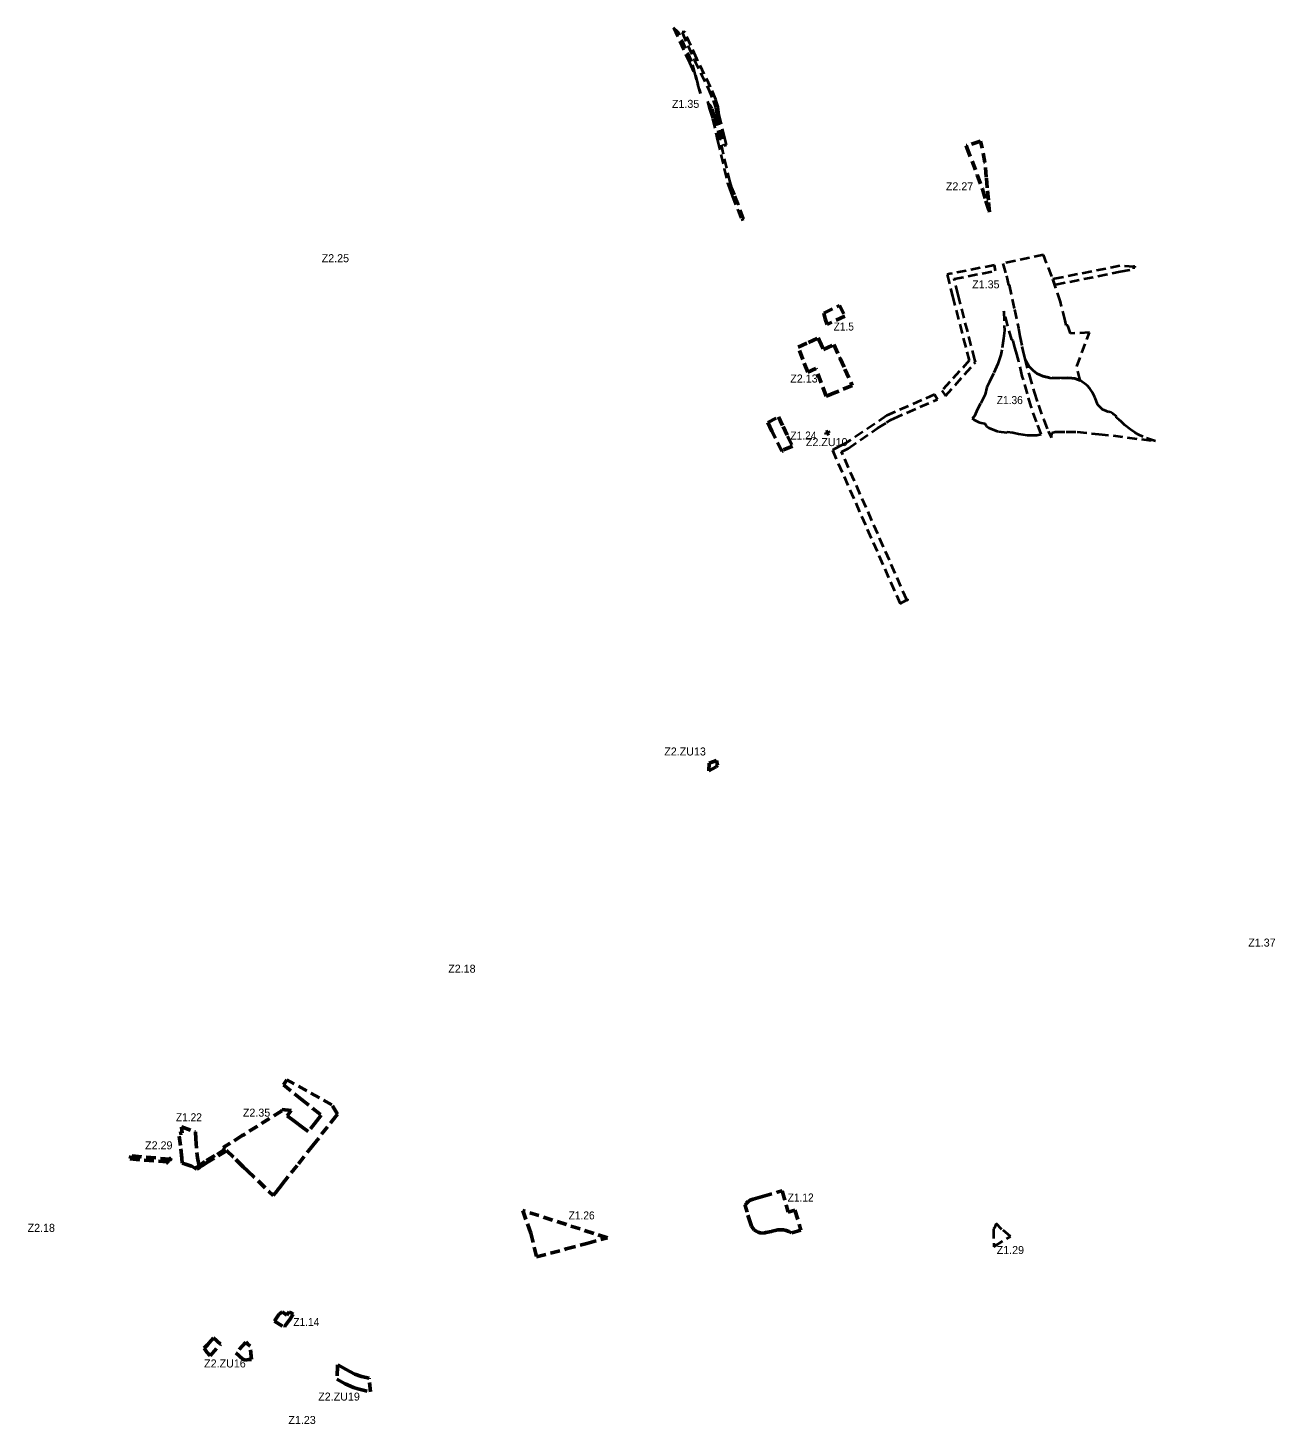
# Model space of a CAD drawing. Extents: x -650368 to -643203, y -1074215 to -1066658.
# Drawn here: x -650368 to -647095, y -1070321 to -1066658 of the extents above; entities that cross this region are included whole.
import ezdxf
from ezdxf.enums import TextEntityAlignment as Align

# ---------------------------------------------------------------- set-up
doc = ezdxf.new("R2010")
doc.units = 0
doc.header["$LTSCALE"] = 8.4
doc.header["$PDMODE"] = 32
doc.header["$PDSIZE"] = 4.2
doc.linetypes.add('MEDIUM_DASHED', pattern=[4.5, 3, -1.5])
doc.layers.add('57', color=7, linetype='MEDIUM_DASHED', lineweight=40)
doc.layers.add('58', color=7, linetype='MEDIUM_DASHED', lineweight=53)
for name, color, linetype in [('60', 7, 'Continuous'), ('61', 7, 'Continuous'), ('62', 7, 'Continuous')]:
    doc.layers.add(name, color=color, linetype=linetype)

msp = doc.modelspace()

# ---------------------------------------------------------------- linework, layer by layer
at = {"layer": '57'}
for p, q in [((-648495.63, -1067161.363), (-648489.1, -1067158.84)), ((-647408.2, -1067742.37), (-647440.81, -1067731.38))]:
    msp.add_line(p, q, dxfattribs=at)
for points in [[(-648602.97, -1066830.11), (-648616.86, -1066779.79), (-648625.44, -1066746.45), (-648659.95, -1066670.89), (-648662.46, -1066668.53), (-648673.407, -1066658.275), (-648631.791, -1066749.394)], [(-648576.145, -1066813.802), (-648612.763, -1066739.165), (-648643.925, -1066668.483), (-648651.042, -1066669.551), (-648651.1, -1066669.56)], [(-648651.1, -1066669.56), (-648619.11, -1066742.12), (-648582.52, -1066816.7)], [(-648631.791, -1066749.394), (-648616.104, -1066782.727), (-648602.97, -1066830.11)], [(-648582.52, -1066816.7), (-648569.13, -1066848.61), (-648566.63, -1066856.72), (-648563.48, -1066866.96), (-648560.2, -1066888.58), (-648541.521, -1066966.657), (-648534.701, -1066965.077), (-648538.812, -1066947.891)], [(-648538.812, -1066947.891), (-648553.323, -1066887.238), (-648556.637, -1066865.397), (-648559.94, -1066854.66), (-648562.542, -1066846.219), (-648576.145, -1066813.802)], [(-648571.96, -1066869.37), (-648577.99, -1066860.17), (-648583.94, -1066851.11), (-648578.702, -1066871.259)], [(-648578.702, -1066871.259), (-648571.167, -1066896.326), (-648557.816, -1066953.444)], [(-648489.1, -1067158.84), (-648512.95, -1067095.97), (-648520.4, -1067077.42), (-648524.93, -1067063.35), (-648533.66, -1067026), (-648551, -1066951.85), (-648564.4, -1066894.52), (-648571.96, -1066869.37)], [(-648557.816, -1066953.444), (-648540.476, -1067027.594), (-648531.681, -1067065.222)], [(-648531.681, -1067065.222), (-648526.988, -1067079.8), (-648519.471, -1067098.516), (-648495.644, -1067161.326)], [(-647638.68, -1067439.06), (-647642.686, -1067438.46), (-647645.78, -1067425.81), (-647658.13, -1067376.99), (-647680.64, -1067310.37), (-647702.42, -1067253.98), (-647809.02, -1067276.271)], [(-647809.02, -1067276.271), (-647799.76, -1067308.3), (-647794.54, -1067333.14)], [(-647948.488, -1067303.671), (-647955.805, -1067305.106), (-647941.289, -1067362.104)], [(-647882.66, -1067529.231), (-647926.759, -1067358.379), (-647937.355, -1067316.774), (-647828.376, -1067295.406), (-647828.104, -1067295.352), (-647831.28, -1067280.69), (-647948.488, -1067303.671)], [(-647465.203, -1067285.115), (-647501.968, -1067282.642), (-647673.685, -1067316.666), (-647678.21, -1067317.562), (-647673.367, -1067331.895), (-647670.77, -1067331.38), (-647501.099, -1067297.762)], [(-647501.099, -1067297.762), (-647465.699, -1067290.747), (-647465.203, -1067285.115)], [(-647794.54, -1067333.14), (-647792.52, -1067332.74), (-647778.78, -1067397.1), (-647768.5, -1067446.04), (-647764.89, -1067466.64), (-647759.16, -1067494.01)], [(-647941.289, -1067362.104), (-647897.637, -1067531.223), (-647969.29, -1067609.79), (-647959.832, -1067623.65)], [(-647773.96, -1067508.48), (-647777.55, -1067496.95), (-647781.85, -1067479.19), (-647785.64, -1067477.02), (-647806.8, -1067401.51), (-647804.88, -1067452.07), (-647807.17, -1067473.06), (-647811.8, -1067502.42), (-647814.89, -1067515.91), (-647822.82, -1067539.89), (-647833.51, -1067565.03), (-647844.04, -1067587.17)], [(-647751.41, -1067526.58), (-647740.124, -1067546.265), (-647729.802, -1067557.462), (-647719.661, -1067564.884), (-647704.458, -1067572.034), (-647685.968, -1067576.68), (-647654.743, -1067576.996), (-647640.087, -1067576.306), (-647628.441, -1067576.759), (-647620.586, -1067578.478), (-647606.559, -1067583.309), (-647614.75, -1067546.53), (-647582.2, -1067457.65), (-647631.59, -1067459.72), (-647638.68, -1067439.06)], [(-647759.16, -1067494.01), (-647756.55, -1067505.32), (-647751.41, -1067526.58)], [(-647959.832, -1067623.65), (-647881.085, -1067535.333), (-647882.66, -1067529.231)], [(-647708.71, -1067723.99), (-647721.05, -1067691.73), (-647734.63, -1067652.57), (-647744.61, -1067617.96), (-647758.25, -1067571.79), (-647768.5, -1067529.75), (-647773.96, -1067508.48)], [(-647547.663, -1067659.519), (-647560.187, -1067647.458), (-647567.744, -1067627.24), (-647573.605, -1067614.951), (-647580.539, -1067604.432), (-647586.864, -1067597.411), (-647591.227, -1067593.613), (-647604.415, -1067584.047), (-647620.586, -1067578.478), (-647628.441, -1067576.759), (-647640.087, -1067576.306), (-647654.743, -1067576.996), (-647685.968, -1067576.68), (-647704.458, -1067572.034), (-647719.661, -1067564.884), (-647729.802, -1067557.462), (-647740.124, -1067546.265), (-647751.41, -1067526.58)], [(-647751.41, -1067526.58), (-647740.49, -1067568.67), (-647727.37, -1067614.33), (-647715.92, -1067648.12), (-647702.04, -1067686.86), (-647690.09, -1067716.05), (-647681.91, -1067732.74)], [(-647844.04, -1067587.17), (-647850.96, -1067600.4), (-647855.65, -1067620.33), (-647867.53, -1067643.84)], [(-647988.235, -1067619.912), (-648114.145, -1067675.531), (-648222.872, -1067748.412), (-648238.748, -1067756.759), (-648256.499, -1067766.091), (-648079.002, -1068168.139), (-648061.329, -1068158.649)], [(-648215.115, -1067761.28), (-648137.869, -1067708.325), (-648114.323, -1067693.403), (-648103.383, -1067686.47), (-648103.298, -1067686.416), (-648095.475, -1067682.994), (-647983.403, -1067633.963), (-647983.06, -1067633.813), (-647980.561, -1067632.719), (-647982.95, -1067628.73), (-647988.235, -1067619.912)], [(-647867.53, -1067643.84), (-647876.15, -1067658.82), (-647883.78, -1067676.59), (-647886.95, -1067680.13), (-647889.94, -1067681.81)], [(-647889.94, -1067681.81), (-647884.25, -1067686.21), (-647882.82, -1067687.32), (-647871.87, -1067692.85), (-647869.32, -1067693.61), (-647865.76, -1067694.68), (-647856.9, -1067695.97)], [(-647499.095, -1067691.163), (-647503.97, -1067686.73), (-647510.6, -1067680.86), (-647511.24, -1067677.53), (-647517.74, -1067672.85), (-647520.13, -1067671.13), (-647527.76, -1067665.65), (-647530.82, -1067666.65), (-647536.83, -1067663.64), (-647547.663, -1067659.519)], [(-647856.9, -1067695.97), (-647852.3, -1067703.36), (-647845.74, -1067707.59), (-647821.02, -1067717.33), (-647798.5, -1067719.67), (-647798.17, -1067717.58), (-647783.13, -1067719.68), (-647768.53, -1067722.82), (-647745.41, -1067726.6), (-647732.71, -1067727.02), (-647720.45, -1067726.49), (-647708.71, -1067723.99)], [(-647681.91, -1067732.74), (-647680.804, -1067720.745), (-647672, -1067718), (-647643, -1067718), (-647614, -1067718), (-647557, -1067724), (-647520.145, -1067727.879), (-647408.2, -1067742.37)], [(-647440.81, -1067731.38), (-647453.87, -1067724.97), (-647462.45, -1067719.84), (-647474.13, -1067711.81), (-647489.3, -1067700.07), (-647499.095, -1067691.163)], [(-648061.329, -1068158.649), (-648232.676, -1067770.513), (-648215.115, -1067761.28)]]:
    msp.add_lwpolyline(points, dxfattribs=at)
at = {"layer": '57', "lineweight": 53}
for points in [[(-648279.24, -1067406.38), (-648237.881, -1067386.158), (-648237.873, -1067386.174), (-648237.865, -1067386.17), (-648224.19, -1067414.14), (-648270.02, -1067436.37), (-648275.41, -1067421.3)], [(-648397.98, -1067678.79), (-648385.86, -1067704.19), (-648373.99, -1067728.95), (-648361.08, -1067755.88), (-648387.04, -1067765.67), (-648386.12, -1067767.45), (-648389.29, -1067768.64), (-648415.164, -1067716.136), (-648426.366, -1067693.402)], [(-649967.81, -1069590.74), (-649971.38, -1069558.79), (-649963.43, -1069557.91), (-649965.26, -1069541.51), (-649928.48, -1069554.57), (-649927.304, -1069572.44), (-649924.62, -1069608.53), (-649923.17, -1069623.14), (-649918.354, -1069643.452), (-649917.38, -1069647.56), (-649924.8, -1069652.19), (-649928.67, -1069649.89), (-649938.2, -1069644.23), (-649954.38, -1069639.1), (-649962.71, -1069636.46), (-649964.11, -1069623.91)], [(-648339.05, -1069812.45), (-648363.68, -1069819.31), (-648371.21, -1069815.56), (-648378.1, -1069813.29), (-648385.21, -1069811.91), (-648392.45, -1069811.44), (-648399.68, -1069811.88), (-648406.84, -1069813.23), (-648414.657, -1069815.246), (-648415.99, -1069815.59), (-648430.881, -1069818.663), (-648433.97, -1069819.3), (-648439.89, -1069819.97), (-648445.8, -1069819.51), (-648451.53, -1069817.98), (-648456.88, -1069815.39), (-648461.64, -1069811.86), (-648465.67, -1069807.49), (-648468.82, -1069802.44), (-648470.97, -1069796.9), (-648480.267, -1069765.316), (-648485.44, -1069747.39), (-648485.14, -1069746.55), (-648483.274, -1069743.777), (-648481.79, -1069741.57), (-648477.39, -1069737.44), (-648476.022, -1069736.525), (-648472.4, -1069734.1), (-648464.45, -1069730.89), (-648439.8, -1069724.19), (-648401.288, -1069713.154), (-648388.631, -1069709.738), (-648372.639, -1069765.241), (-648355.015, -1069760.287)], [(-649069.4, -1069760.67), (-649048, -1069820), (-649032.928, -1069882.782), (-648955.211, -1069861.806), (-648901.185, -1069847.225), (-648846.924, -1069832.58)], [(-649676.46, -1070039.89), (-649671.82, -1070033.15), (-649678.92, -1070028.51), (-649682.07, -1070026.45), (-649686.55, -1070033.29), (-649688.24, -1070035.47), (-649692, -1070033.14), (-649691.64, -1070032.56), (-649700.69, -1070026.36), (-649709.67, -1070034.09), (-649718.51, -1070046.94), (-649721.11, -1070051.18), (-649694.06, -1070067.08), (-649693.23, -1070065.13), (-649691.7, -1070062.02), (-649685.84, -1070053.65), (-649679.2, -1070044.17)]]:
    msp.add_lwpolyline(points, close=True, dxfattribs=at)
at = {"layer": '57'}
msp.add_lwpolyline([(-647833.172, -1069855.944), (-647833.172, -1069855.944), (-647831.62, -1069854.99), (-647789.55, -1069829.12), (-647811.83, -1069810.39), (-647827.16, -1069795.32), (-647831.32, -1069806.56), (-647833.91, -1069808.91), (-647833.2, -1069854.15)], close=True, dxfattribs=at)
for p in [(-647465.203, -1067285.115), (-648061.329, -1068158.649)]:
    msp.add_point(p, dxfattribs=at)
at = {"layer": '58'}
for points in [[(-647903.5, -1066972.05), (-647876.57, -1067043.5), (-647863.04, -1067081.36), (-647853.65, -1067111.91), (-647844.3, -1067141.25), (-647847.09, -1067110.58), (-647850.07, -1067077.71), (-647852.63, -1067049.52), (-647856.11, -1067011.21), (-647866.14, -1066961.98), (-647867.46, -1066955.52), (-647905.28, -1066967.07)], [(-648254.04, -1067616.96), (-648265.601, -1067621.762), (-648272.941, -1067624.811), (-648299.23, -1067554.52), (-648300.258, -1067551.772), (-648321.36, -1067561.69), (-648334.09, -1067528.2), (-648346.27, -1067496.14), (-648319.7, -1067483.53), (-648319.7, -1067483.53), (-648294.04, -1067471.35), (-648291.17, -1067477.57), (-648279.86, -1067502.11), (-648253.1, -1067489.23), (-648237.81, -1067522.42), (-648236.51, -1067525.24), (-648223.55, -1067553.354), (-648204.88, -1067596.54)], [(-648267.25, -1067716.9), (-648273.97, -1067719.29), (-648272.02, -1067724.45), (-648269.15, -1067723.37), (-648264.95, -1067721.79)], [(-648579.97, -1068587.39), (-648580.66, -1068607.64), (-648561.49, -1068596.84), (-648558.08, -1068592.36), (-648560.79, -1068580.12)], [(-650002.39, -1069633.65), (-649994.913, -1069626.246), (-650096.627, -1069617.746), (-650099.55, -1069625.53), (-650062.45, -1069628.63)], [(-649897.03, -1070113.07), (-649905.51, -1070122.35), (-649898.55, -1070132.9), (-649889.87, -1070141.83), (-649862.22, -1070111.54), (-649880.42, -1070094.87), (-649886.83, -1070101.89)], [(-649784.87, -1070116.76), (-649791.58, -1070110.83), (-649796.4, -1070106.56), (-649821.97, -1070134.58), (-649804.29, -1070150.68), (-649797.33, -1070153.41), (-649787.92, -1070152.23), (-649781.432, -1070151.628)], [(-649557.21, -1070203.53), (-649535, -1070216), (-649513, -1070225), (-649502.36, -1070228.94), (-649469.02, -1070236.92), (-649472.43, -1070202.9), (-649472.6, -1070201.15), (-649492.67, -1070196.34), (-649509.72, -1070190.24), (-649523.21, -1070183.06), (-649532.57, -1070178.08), (-649555.44, -1070165.91), (-649555.15, -1070169.51)]]:
    msp.add_lwpolyline(points, close=True, dxfattribs=at)
for points in [[(-649688.625, -1069418.156), (-649697.525, -1069431.522), (-649650.425, -1069468.85), (-649619.983, -1069493.184), (-649598.004, -1069510.814), (-649610.429, -1069526.497), (-649632.179, -1069553.95), (-649649.31, -1069541.16), (-649667.74, -1069527.4), (-649687.77, -1069512.44), (-649677.02, -1069498.32), (-649701.7, -1069495.89), (-649701.57, -1069499.21), (-649801.49, -1069561.98), (-649805.22, -1069564.32), (-649855.34, -1069595.8), (-649850.24, -1069600.295), (-649877.129, -1069617.006), (-649903.292, -1069632.541), (-649918.35, -1069643.45), (-649928.67, -1069649.89), (-649924.8, -1069652.19), (-649920.45, -1069649.53), (-649917.38, -1069647.56), (-649907.07, -1069640.92), (-649900.64, -1069636.78), (-649846.38, -1069603.8), (-649822.26, -1069627.2), (-649818.71, -1069630.64), (-649802.9, -1069645.96), (-649791.3, -1069657.21)], [(-649561.17, -1069515.83), (-649558.71, -1069512.62), (-649555.16, -1069508.07), (-649570.03, -1069483.83), (-649688.625, -1069418.156)], [(-649620.45, -1069590.75), (-649574.1, -1069531.97), (-649571.94, -1069529.24), (-649561.17, -1069515.83)], [(-649724.51, -1069721.57), (-649714.03, -1069709.09), (-649712.64, -1069707.43), (-649705.28, -1069698.11), (-649700.42, -1069691.8), (-649658.13, -1069638.84), (-649620.45, -1069590.75)], [(-649791.3, -1069657.21), (-649763.31, -1069683.5), (-649763.31, -1069683.5), (-649724.51, -1069721.57)]]:
    msp.add_lwpolyline(points, dxfattribs=at)
for p in [(-650002.39, -1069633.65), (-649994.913, -1069626.246)]:
    msp.add_point(p, dxfattribs=at)

# ---------------------------------------------------------------- texts
at = {"layer": '60'}
for s, p in [('Z1.35', (-648641.847, -1066868.029)), ('Z1.35', (-647853.88, -1067341.475)), ('Z1.37', (-647129.255, -1069068.508)), ('Z1.29', (-647789.527, -1069875.149)), ('Z1.23', (-649648.392, -1070320.945))]:
    msp.add_text(s, height=21, dxfattribs=at).set_placement(p, align=Align.CENTER)
at = {"layer": '60', "width": 0.95}
for s, p in [('Z1.5', (-648226.743, -1067452.194)), ('Z1.36', (-647790.96, -1067645.188)), ('Z1.24', (-648332.556, -1067738.122)), ('Z1.22', (-649945.368, -1069526.711)), ('Z1.12', (-648339.89, -1069737.306)), ('Z1.26', (-648914.702, -1069784.313)), ('Z1.14', (-649637.253, -1070063.973))]:
    msp.add_text(s, height=21, dxfattribs=at).set_placement(p, align=Align.CENTER)
at = {"layer": '61'}
for s, p in [('Z2.27', (-647922.882, -1067084.411)), ('Z2.13', (-648331.178, -1067588.562)), ('Z2.ZU10', (-648271.539, -1067755.404)), ('Z2.ZU13', (-648643.248, -1068567.089)), ('Z2.35', (-649767.849, -1069514.654)), ('Z2.29', (-650024.478, -1069600.414)), ('Z2.ZU16', (-649850.907, -1070172.691)), ('Z2.ZU19', (-649551.432, -1070259.616))]:
    msp.add_text(s, height=21, dxfattribs=at).set_placement(p, align=Align.CENTER)
at = {"layer": '62'}
for s, p in [('Z2.25', (-649561.009, -1067272.925)), ('Z2.18', (-649228.931, -1069136.994)), ('Z2.18', (-650332.906, -1069816.873))]:
    msp.add_text(s, height=21, dxfattribs=at).set_placement(p, align=Align.CENTER)

doc.saveas('drawing.dxf')
